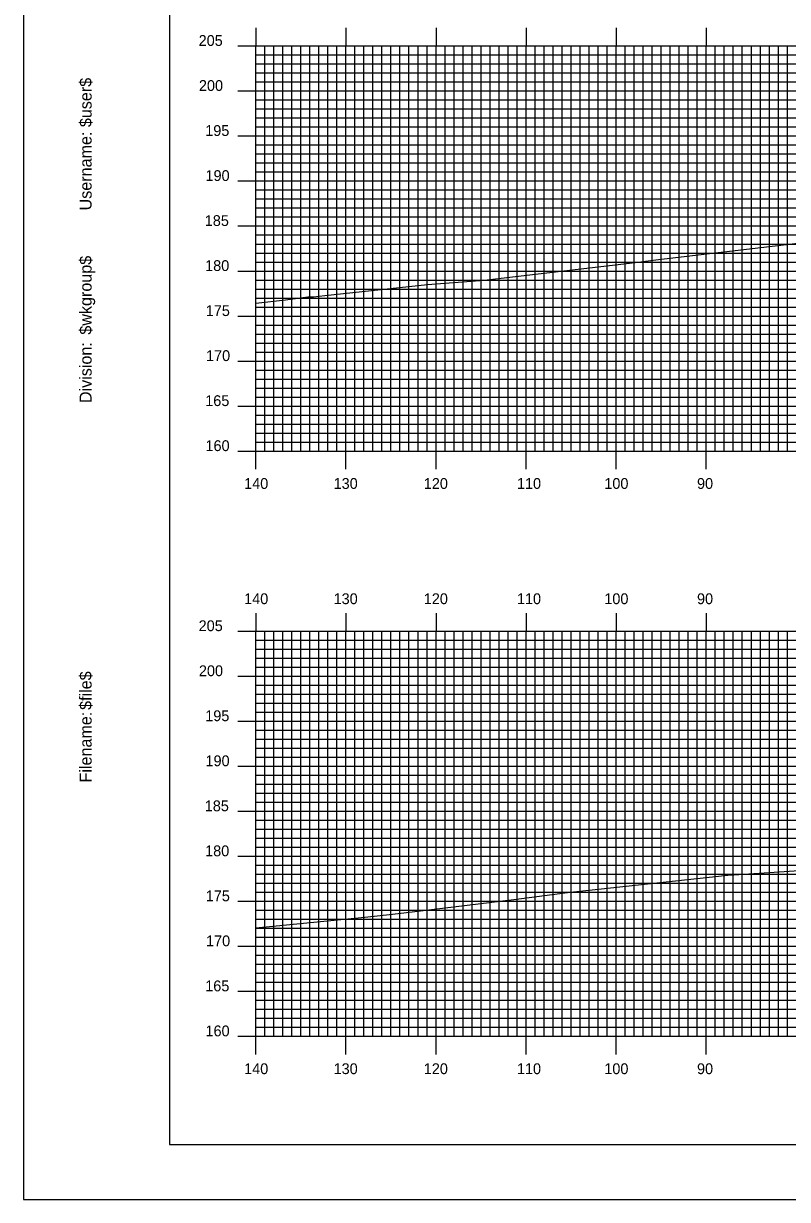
# Model space of a CAD drawing. Extents: x 1794453 to 1794796, y 442591 to 442811.
# Drawn here: x 1794452.6 to 1794537.4, y 442590.5 to 442721.2 of the extents above; entities that cross this region are included whole.
import ezdxf

# ---------------------------------------------------------------- set-up
doc = ezdxf.new("R2010")
doc.units = 0
for name, color, linetype in [('BORDER', 7, 'Continuous'), ('H_V ANNOTATION', 7, 'Continuous'), ('MAJOR', 7, 'Continuous'), ('MINOR', 7, 'Continuous'), ('PLOT BOUNDARY', 7, 'Continuous'), ('S_Roadway_Centerline', 7, 'Continuous')]:
    doc.layers.add(name, color=color, linetype=linetype)

msp = doc.modelspace()

# ---------------------------------------------------------------- linework, layer by layer
at = {"layer": 'BORDER'}
msp.add_lwpolyline([(1794468.74, 442596.67), (1794788.74, 442596.67), (1794788.74, 442806.67), (1794468.74, 442806.67)], close=True, dxfattribs=at)
at = {"layer": 'MAJOR'}
for p, q in [((1794478.34, 442720.67), (1794478.34, 442718.67)), ((1794488.34, 442720.67), (1794488.34, 442718.67)), ((1794498.34, 442720.67), (1794498.34, 442718.67)), ((1794508.34, 442720.67), (1794508.34, 442718.67)), ((1794518.34, 442720.67), (1794518.34, 442718.67)), ((1794528.34, 442720.67), (1794528.34, 442718.67)), ((1794476.34, 442718.67), (1794478.34, 442718.67)), ((1794478.34, 442718.67), (1794758.34, 442718.67)), ((1794478.34, 442673.67), (1794478.34, 442718.67)), ((1794478.34, 442673.67), (1794478.34, 442718.67)), ((1794478.34, 442718.67), (1794758.34, 442718.67)), ((1794488.34, 442673.67), (1794488.34, 442718.67)), ((1794498.34, 442673.67), (1794498.34, 442718.67)), ((1794508.34, 442673.67), (1794508.34, 442718.67)), ((1794518.34, 442673.67), (1794518.34, 442718.67)), ((1794528.34, 442673.67), (1794528.34, 442718.67)), ((1794476.34, 442713.67), (1794478.34, 442713.67)), ((1794478.34, 442713.67), (1794758.34, 442713.67)), ((1794476.34, 442708.67), (1794478.34, 442708.67)), ((1794478.34, 442708.67), (1794758.34, 442708.67)), ((1794476.34, 442703.67), (1794478.34, 442703.67)), ((1794478.34, 442703.67), (1794758.34, 442703.67)), ((1794476.34, 442698.67), (1794478.34, 442698.67)), ((1794478.34, 442698.67), (1794758.34, 442698.67)), ((1794476.34, 442693.67), (1794478.34, 442693.67)), ((1794478.34, 442693.67), (1794758.34, 442693.67)), ((1794476.34, 442688.67), (1794478.34, 442688.67)), ((1794478.34, 442688.67), (1794758.34, 442688.67)), ((1794476.34, 442683.67), (1794478.34, 442683.67)), ((1794478.34, 442683.67), (1794758.34, 442683.67)), ((1794476.34, 442678.67), (1794478.34, 442678.67)), ((1794478.34, 442678.67), (1794758.34, 442678.67)), ((1794476.34, 442673.67), (1794478.34, 442673.67)), ((1794478.34, 442673.67), (1794758.34, 442673.67)), ((1794478.34, 442673.67), (1794758.34, 442673.67)), ((1794478.34, 442671.66), (1794478.34, 442673.67)), ((1794488.34, 442671.66), (1794488.34, 442673.67)), ((1794498.34, 442671.66), (1794498.34, 442673.67)), ((1794508.34, 442671.66), (1794508.34, 442673.67)), ((1794518.34, 442671.66), (1794518.34, 442673.67)), ((1794528.34, 442671.66), (1794528.34, 442673.67)), ((1794478.34, 442655.67), (1794478.34, 442653.67)), ((1794488.34, 442655.67), (1794488.34, 442653.67)), ((1794498.34, 442655.67), (1794498.34, 442653.67)), ((1794508.34, 442655.67), (1794508.34, 442653.67)), ((1794518.34, 442655.67), (1794518.34, 442653.67)), ((1794528.34, 442655.67), (1794528.34, 442653.67)), ((1794476.34, 442653.67), (1794478.34, 442653.67)), ((1794478.34, 442653.67), (1794758.34, 442653.67)), ((1794478.34, 442608.67), (1794478.34, 442653.67)), ((1794478.34, 442608.67), (1794478.34, 442653.67)), ((1794478.34, 442653.67), (1794758.34, 442653.67)), ((1794488.34, 442608.67), (1794488.34, 442653.67)), ((1794498.34, 442608.67), (1794498.34, 442653.67)), ((1794508.34, 442608.67), (1794508.34, 442653.67)), ((1794518.34, 442608.67), (1794518.34, 442653.67)), ((1794528.34, 442608.67), (1794528.34, 442653.67)), ((1794476.34, 442648.67), (1794478.34, 442648.67)), ((1794478.34, 442648.67), (1794758.34, 442648.67)), ((1794476.34, 442643.67), (1794478.34, 442643.67)), ((1794478.34, 442643.67), (1794758.34, 442643.67)), ((1794476.34, 442638.67), (1794478.34, 442638.67)), ((1794478.34, 442638.67), (1794758.34, 442638.67)), ((1794476.34, 442633.67), (1794478.34, 442633.67)), ((1794478.34, 442633.67), (1794758.34, 442633.67)), ((1794476.34, 442628.67), (1794478.34, 442628.67)), ((1794478.34, 442628.67), (1794758.34, 442628.67)), ((1794476.34, 442623.67), (1794478.34, 442623.67)), ((1794478.34, 442623.67), (1794758.34, 442623.67)), ((1794476.34, 442618.67), (1794478.34, 442618.67)), ((1794478.34, 442618.67), (1794758.34, 442618.67)), ((1794476.34, 442613.67), (1794478.34, 442613.67)), ((1794478.34, 442613.67), (1794758.34, 442613.67)), ((1794476.34, 442608.67), (1794478.34, 442608.67)), ((1794478.34, 442608.67), (1794758.34, 442608.67)), ((1794478.34, 442608.67), (1794758.34, 442608.67)), ((1794478.34, 442606.66), (1794478.34, 442608.67)), ((1794488.34, 442606.66), (1794488.34, 442608.67)), ((1794498.34, 442606.66), (1794498.34, 442608.67)), ((1794508.34, 442606.66), (1794508.34, 442608.67)), ((1794518.34, 442606.66), (1794518.34, 442608.67)), ((1794528.34, 442606.66), (1794528.34, 442608.67))]:
    msp.add_line(p, q, dxfattribs=at)
at = {"layer": 'MINOR'}
for p, q in [((1794479.34, 442673.67), (1794479.34, 442718.67)), ((1794480.34, 442673.67), (1794480.34, 442718.67)), ((1794481.34, 442673.67), (1794481.34, 442718.67)), ((1794482.34, 442673.67), (1794482.34, 442718.67)), ((1794483.34, 442673.67), (1794483.34, 442718.67)), ((1794484.34, 442673.67), (1794484.34, 442718.67)), ((1794485.34, 442673.67), (1794485.34, 442718.67)), ((1794486.34, 442673.67), (1794486.34, 442718.67)), ((1794487.34, 442673.67), (1794487.34, 442718.67)), ((1794489.34, 442673.67), (1794489.34, 442718.67)), ((1794490.34, 442673.67), (1794490.34, 442718.67)), ((1794491.34, 442673.67), (1794491.34, 442718.67)), ((1794492.34, 442673.67), (1794492.34, 442718.67)), ((1794493.34, 442673.67), (1794493.34, 442718.67)), ((1794494.34, 442673.67), (1794494.34, 442718.67)), ((1794495.34, 442673.67), (1794495.34, 442718.67)), ((1794496.34, 442673.67), (1794496.34, 442718.67)), ((1794497.34, 442673.67), (1794497.34, 442718.67)), ((1794499.34, 442673.67), (1794499.34, 442718.67)), ((1794500.34, 442673.67), (1794500.34, 442718.67)), ((1794501.34, 442673.67), (1794501.34, 442718.67)), ((1794502.34, 442673.67), (1794502.34, 442718.67)), ((1794503.34, 442673.67), (1794503.34, 442718.67)), ((1794504.34, 442673.67), (1794504.34, 442718.67)), ((1794505.34, 442673.67), (1794505.34, 442718.67)), ((1794506.34, 442673.67), (1794506.34, 442718.67)), ((1794507.34, 442673.67), (1794507.34, 442718.67)), ((1794509.34, 442673.67), (1794509.34, 442718.67)), ((1794510.34, 442673.67), (1794510.34, 442718.67)), ((1794511.34, 442673.67), (1794511.34, 442718.67)), ((1794512.34, 442673.67), (1794512.34, 442718.67)), ((1794513.34, 442673.67), (1794513.34, 442718.67)), ((1794514.34, 442673.67), (1794514.34, 442718.67)), ((1794515.34, 442673.67), (1794515.34, 442718.67)), ((1794516.34, 442673.67), (1794516.34, 442718.67)), ((1794517.34, 442673.67), (1794517.34, 442718.67)), ((1794519.34, 442673.67), (1794519.34, 442718.67)), ((1794520.34, 442673.67), (1794520.34, 442718.67)), ((1794521.34, 442673.67), (1794521.34, 442718.67)), ((1794522.34, 442673.67), (1794522.34, 442718.67)), ((1794523.34, 442673.67), (1794523.34, 442718.67)), ((1794524.34, 442673.67), (1794524.34, 442718.67)), ((1794525.34, 442673.67), (1794525.34, 442718.67)), ((1794526.34, 442673.67), (1794526.34, 442718.67)), ((1794527.34, 442673.67), (1794527.34, 442718.67)), ((1794529.34, 442673.67), (1794529.34, 442718.67)), ((1794530.34, 442673.67), (1794530.34, 442718.67)), ((1794531.34, 442673.67), (1794531.34, 442718.67)), ((1794532.34, 442673.67), (1794532.34, 442718.67)), ((1794533.34, 442673.67), (1794533.34, 442718.67)), ((1794534.34, 442673.67), (1794534.34, 442718.67)), ((1794535.34, 442673.67), (1794535.34, 442718.67)), ((1794536.34, 442673.67), (1794536.34, 442718.67)), ((1794537.34, 442673.67), (1794537.34, 442718.67)), ((1794478.34, 442717.67), (1794758.34, 442717.67)), ((1794478.34, 442717.67), (1794480.34, 442717.67)), ((1794478.34, 442716.67), (1794758.34, 442716.67)), ((1794478.34, 442716.67), (1794480.34, 442716.67)), ((1794478.34, 442715.67), (1794758.34, 442715.67)), ((1794478.34, 442715.67), (1794480.34, 442715.67)), ((1794478.34, 442714.67), (1794758.34, 442714.67)), ((1794478.34, 442714.67), (1794480.34, 442714.67)), ((1794478.34, 442712.67), (1794758.34, 442712.67)), ((1794478.34, 442712.67), (1794480.34, 442712.67)), ((1794478.34, 442711.67), (1794758.34, 442711.67)), ((1794478.34, 442711.67), (1794480.34, 442711.67)), ((1794478.34, 442710.67), (1794758.34, 442710.67)), ((1794478.34, 442710.67), (1794480.34, 442710.67)), ((1794478.34, 442709.67), (1794758.34, 442709.67)), ((1794478.34, 442709.67), (1794480.34, 442709.67)), ((1794478.34, 442707.67), (1794758.34, 442707.67)), ((1794478.34, 442707.67), (1794480.34, 442707.67)), ((1794478.34, 442706.67), (1794758.34, 442706.67)), ((1794478.34, 442706.67), (1794480.34, 442706.67)), ((1794478.34, 442705.67), (1794758.34, 442705.67)), ((1794478.34, 442705.67), (1794480.34, 442705.67)), ((1794478.34, 442704.67), (1794758.34, 442704.67)), ((1794478.34, 442704.67), (1794480.34, 442704.67)), ((1794478.34, 442702.67), (1794758.34, 442702.67)), ((1794478.34, 442702.67), (1794480.34, 442702.67)), ((1794478.34, 442701.67), (1794758.34, 442701.67)), ((1794478.34, 442701.67), (1794480.34, 442701.67)), ((1794478.34, 442700.67), (1794758.34, 442700.67)), ((1794478.34, 442700.67), (1794480.34, 442700.67)), ((1794478.34, 442699.67), (1794758.34, 442699.67)), ((1794478.34, 442699.67), (1794480.34, 442699.67)), ((1794478.34, 442697.67), (1794758.34, 442697.67)), ((1794478.34, 442697.67), (1794480.34, 442697.67)), ((1794478.34, 442696.67), (1794758.34, 442696.67)), ((1794478.34, 442696.67), (1794480.34, 442696.67)), ((1794478.34, 442695.67), (1794758.34, 442695.67)), ((1794478.34, 442695.67), (1794480.34, 442695.67)), ((1794478.34, 442694.67), (1794758.34, 442694.67)), ((1794478.34, 442694.67), (1794480.34, 442694.67)), ((1794478.34, 442692.67), (1794758.34, 442692.67)), ((1794478.34, 442692.67), (1794480.34, 442692.67)), ((1794478.34, 442691.67), (1794758.34, 442691.67)), ((1794478.34, 442691.67), (1794480.34, 442691.67)), ((1794478.34, 442690.67), (1794758.34, 442690.67)), ((1794478.34, 442690.67), (1794480.34, 442690.67)), ((1794478.34, 442689.67), (1794758.34, 442689.67)), ((1794478.34, 442689.67), (1794480.34, 442689.67)), ((1794478.34, 442687.67), (1794758.34, 442687.67)), ((1794478.34, 442687.67), (1794480.34, 442687.67)), ((1794478.34, 442686.67), (1794758.34, 442686.67)), ((1794478.34, 442686.67), (1794480.34, 442686.67)), ((1794478.34, 442685.67), (1794758.34, 442685.67)), ((1794478.34, 442685.67), (1794480.34, 442685.67)), ((1794478.34, 442684.67), (1794758.34, 442684.67)), ((1794478.34, 442684.67), (1794480.34, 442684.67)), ((1794478.34, 442682.67), (1794758.34, 442682.67)), ((1794478.34, 442682.67), (1794480.34, 442682.67)), ((1794478.34, 442681.67), (1794758.34, 442681.67)), ((1794478.34, 442681.67), (1794480.34, 442681.67)), ((1794478.34, 442680.67), (1794758.34, 442680.67)), ((1794478.34, 442680.67), (1794480.34, 442680.67)), ((1794478.34, 442679.67), (1794758.34, 442679.67)), ((1794478.34, 442679.67), (1794480.34, 442679.67)), ((1794478.34, 442677.67), (1794758.34, 442677.67)), ((1794478.34, 442677.67), (1794480.34, 442677.67)), ((1794478.34, 442676.67), (1794758.34, 442676.67)), ((1794478.34, 442676.67), (1794480.34, 442676.67)), ((1794478.34, 442675.67), (1794758.34, 442675.67)), ((1794478.34, 442675.67), (1794480.34, 442675.67)), ((1794478.34, 442674.67), (1794758.34, 442674.67)), ((1794478.34, 442674.67), (1794480.34, 442674.67)), ((1794478.34, 442652.67), (1794758.34, 442652.67)), ((1794478.34, 442652.67), (1794480.34, 442652.67)), ((1794479.34, 442608.67), (1794479.34, 442653.67)), ((1794480.34, 442608.67), (1794480.34, 442653.67)), ((1794481.34, 442608.67), (1794481.34, 442653.67)), ((1794482.34, 442608.67), (1794482.34, 442653.67)), ((1794483.34, 442608.67), (1794483.34, 442653.67)), ((1794484.34, 442608.67), (1794484.34, 442653.67)), ((1794485.34, 442608.67), (1794485.34, 442653.67)), ((1794486.34, 442608.67), (1794486.34, 442653.67)), ((1794487.34, 442608.67), (1794487.34, 442653.67)), ((1794489.34, 442608.67), (1794489.34, 442653.67)), ((1794490.34, 442608.67), (1794490.34, 442653.67)), ((1794491.34, 442608.67), (1794491.34, 442653.67)), ((1794492.34, 442608.67), (1794492.34, 442653.67)), ((1794493.34, 442608.67), (1794493.34, 442653.67)), ((1794494.34, 442608.67), (1794494.34, 442653.67)), ((1794495.34, 442608.67), (1794495.34, 442653.67)), ((1794496.34, 442608.67), (1794496.34, 442653.67)), ((1794497.34, 442608.67), (1794497.34, 442653.67)), ((1794499.34, 442608.67), (1794499.34, 442653.67)), ((1794500.34, 442608.67), (1794500.34, 442653.67)), ((1794501.34, 442608.67), (1794501.34, 442653.67)), ((1794502.34, 442608.67), (1794502.34, 442653.67)), ((1794503.34, 442608.67), (1794503.34, 442653.67)), ((1794504.34, 442608.67), (1794504.34, 442653.67)), ((1794505.34, 442608.67), (1794505.34, 442653.67)), ((1794506.34, 442608.67), (1794506.34, 442653.67)), ((1794507.34, 442608.67), (1794507.34, 442653.67)), ((1794509.34, 442608.67), (1794509.34, 442653.67)), ((1794510.34, 442608.67), (1794510.34, 442653.67)), ((1794511.34, 442608.67), (1794511.34, 442653.67)), ((1794512.34, 442608.67), (1794512.34, 442653.67)), ((1794513.34, 442608.67), (1794513.34, 442653.67)), ((1794514.34, 442608.67), (1794514.34, 442653.67)), ((1794515.34, 442608.67), (1794515.34, 442653.67)), ((1794516.34, 442608.67), (1794516.34, 442653.67)), ((1794517.34, 442608.67), (1794517.34, 442653.67)), ((1794519.34, 442608.67), (1794519.34, 442653.67)), ((1794520.34, 442608.67), (1794520.34, 442653.67)), ((1794521.34, 442608.67), (1794521.34, 442653.67)), ((1794522.34, 442608.67), (1794522.34, 442653.67)), ((1794523.34, 442608.67), (1794523.34, 442653.67)), ((1794524.34, 442608.67), (1794524.34, 442653.67)), ((1794525.34, 442608.67), (1794525.34, 442653.67)), ((1794526.34, 442608.67), (1794526.34, 442653.67)), ((1794527.34, 442608.67), (1794527.34, 442653.67)), ((1794529.34, 442608.67), (1794529.34, 442653.67)), ((1794530.34, 442608.67), (1794530.34, 442653.67)), ((1794531.34, 442608.67), (1794531.34, 442653.67)), ((1794532.34, 442608.67), (1794532.34, 442653.67)), ((1794533.34, 442608.67), (1794533.34, 442653.67)), ((1794534.34, 442608.67), (1794534.34, 442653.67)), ((1794535.34, 442608.67), (1794535.34, 442653.67)), ((1794536.34, 442608.67), (1794536.34, 442653.67)), ((1794537.34, 442608.67), (1794537.34, 442653.67)), ((1794478.34, 442651.67), (1794758.34, 442651.67)), ((1794478.34, 442651.67), (1794480.34, 442651.67)), ((1794478.34, 442650.67), (1794758.34, 442650.67)), ((1794478.34, 442650.67), (1794480.34, 442650.67)), ((1794478.34, 442649.67), (1794758.34, 442649.67)), ((1794478.34, 442649.67), (1794480.34, 442649.67)), ((1794478.34, 442647.67), (1794758.34, 442647.67)), ((1794478.34, 442647.67), (1794480.34, 442647.67)), ((1794478.34, 442646.67), (1794758.34, 442646.67)), ((1794478.34, 442646.67), (1794480.34, 442646.67)), ((1794478.34, 442645.67), (1794758.34, 442645.67)), ((1794478.34, 442645.67), (1794480.34, 442645.67)), ((1794478.34, 442644.67), (1794758.34, 442644.67)), ((1794478.34, 442644.67), (1794480.34, 442644.67)), ((1794478.34, 442642.67), (1794758.34, 442642.67)), ((1794478.34, 442642.67), (1794480.34, 442642.67)), ((1794478.34, 442641.67), (1794758.34, 442641.67)), ((1794478.34, 442641.67), (1794480.34, 442641.67)), ((1794478.34, 442640.67), (1794758.34, 442640.67)), ((1794478.34, 442640.67), (1794480.34, 442640.67)), ((1794478.34, 442639.67), (1794758.34, 442639.67)), ((1794478.34, 442639.67), (1794480.34, 442639.67)), ((1794478.34, 442637.67), (1794758.34, 442637.67)), ((1794478.34, 442637.67), (1794480.34, 442637.67)), ((1794478.34, 442636.67), (1794758.34, 442636.67)), ((1794478.34, 442636.67), (1794480.34, 442636.67)), ((1794478.34, 442635.67), (1794758.34, 442635.67)), ((1794478.34, 442635.67), (1794480.34, 442635.67)), ((1794478.34, 442634.67), (1794758.34, 442634.67)), ((1794478.34, 442634.67), (1794480.34, 442634.67)), ((1794478.34, 442632.67), (1794758.34, 442632.67)), ((1794478.34, 442632.67), (1794480.34, 442632.67)), ((1794478.34, 442631.67), (1794758.34, 442631.67)), ((1794478.34, 442631.67), (1794480.34, 442631.67)), ((1794478.34, 442630.67), (1794758.34, 442630.67)), ((1794478.34, 442630.67), (1794480.34, 442630.67)), ((1794478.34, 442629.67), (1794758.34, 442629.67)), ((1794478.34, 442629.67), (1794480.34, 442629.67)), ((1794478.34, 442627.67), (1794758.34, 442627.67)), ((1794478.34, 442627.67), (1794480.34, 442627.67)), ((1794478.34, 442626.67), (1794758.34, 442626.67)), ((1794478.34, 442626.67), (1794480.34, 442626.67)), ((1794478.34, 442625.67), (1794758.34, 442625.67)), ((1794478.34, 442625.67), (1794480.34, 442625.67)), ((1794478.34, 442624.67), (1794758.34, 442624.67)), ((1794478.34, 442624.67), (1794480.34, 442624.67)), ((1794478.34, 442622.67), (1794758.34, 442622.67)), ((1794478.34, 442622.67), (1794480.34, 442622.67)), ((1794478.34, 442621.67), (1794758.34, 442621.67)), ((1794478.34, 442621.67), (1794480.34, 442621.67)), ((1794478.34, 442620.67), (1794758.34, 442620.67)), ((1794478.34, 442620.67), (1794480.34, 442620.67)), ((1794478.34, 442619.67), (1794758.34, 442619.67)), ((1794478.34, 442619.67), (1794480.34, 442619.67)), ((1794478.34, 442617.67), (1794758.34, 442617.67)), ((1794478.34, 442617.67), (1794480.34, 442617.67)), ((1794478.34, 442616.67), (1794758.34, 442616.67)), ((1794478.34, 442616.67), (1794480.34, 442616.67)), ((1794478.34, 442615.67), (1794758.34, 442615.67)), ((1794478.34, 442615.67), (1794480.34, 442615.67)), ((1794478.34, 442614.67), (1794758.34, 442614.67)), ((1794478.34, 442614.67), (1794480.34, 442614.67)), ((1794478.34, 442612.67), (1794758.34, 442612.67)), ((1794478.34, 442612.67), (1794480.34, 442612.67)), ((1794478.34, 442611.67), (1794758.34, 442611.67)), ((1794478.34, 442611.67), (1794480.34, 442611.67)), ((1794478.34, 442610.67), (1794758.34, 442610.67)), ((1794478.34, 442610.67), (1794480.34, 442610.67)), ((1794478.34, 442609.67), (1794758.34, 442609.67)), ((1794478.34, 442609.67), (1794480.34, 442609.67))]:
    msp.add_line(p, q, dxfattribs=at)
at = {"layer": 'PLOT BOUNDARY'}
msp.add_lwpolyline([(1794452.55, 442590.55), (1794792.55, 442590.55), (1794792.55, 442810.55), (1794452.55, 442810.55)], close=True, dxfattribs=at)
at = {"layer": 'S_Roadway_Centerline'}
for points in [[(1794478.34, 442690.11), (1794481.65, 442690.48), (1794484.12, 442690.79), (1794484.74, 442690.82), (1794486, 442690.96), (1794497.41, 442692.18), (1794503.67, 442692.66), (1794521.06, 442694.7), (1794521.61, 442694.78), (1794521.9, 442694.81), (1794523.03, 442694.94), (1794540.4, 442696.97)], [(1794478.34, 442620.7), (1794490.44, 442621.92), (1794493.51, 442622.22), (1794496.61, 442622.59), (1794506.97, 442623.87), (1794512.93, 442624.64), (1794531.05, 442626.59), (1794531.32, 442626.62), (1794531.41, 442626.62), (1794542.56, 442627.35)]]:
    msp.add_lwpolyline(points, dxfattribs=at)

# ---------------------------------------------------------------- texts
at = {"layer": 'BORDER'}
for s, p in [('$user$', (1794460.11, 442709.65)), ('Username:', (1794460.11, 442700.4)), ('$wkgroup$', (1794460.11, 442686.6)), ('Division:', (1794460.11, 442679)), ('$file$', (1794460.11, 442644.92)), ('Filename:', (1794460.11, 442636.86))]:
    msp.add_text(s, height=1.339, rotation=90, dxfattribs=at).set_placement(p)
at = {"layer": 'H_V ANNOTATION'}
for s, p in [('205', (1794471.99, 442718.67)), ('200', (1794472.02, 442713.67)), ('195', (1794472.72, 442708.67)), ('190', (1794472.75, 442703.67)), ('185', (1794472.67, 442698.67)), ('180', (1794472.71, 442693.67)), ('175', (1794472.78, 442688.67)), ('170', (1794472.81, 442683.67)), ('165', (1794472.72, 442678.67)), ('160', (1794472.75, 442673.67)), ('140', (1794477.04, 442669.47)), ('130', (1794486.97, 442669.47)), ('120', (1794496.98, 442669.47)), ('110', (1794507.32, 442669.47)), ('100', (1794517.02, 442669.47)), ('90', (1794527.31, 442669.47)), ('140', (1794477.04, 442656.67)), ('130', (1794486.97, 442656.67)), ('120', (1794496.98, 442656.67)), ('110', (1794507.32, 442656.67)), ('100', (1794517.02, 442656.67)), ('90', (1794527.31, 442656.67)), ('205', (1794471.99, 442653.67)), ('200', (1794472.02, 442648.67)), ('195', (1794472.72, 442643.67)), ('190', (1794472.75, 442638.67)), ('185', (1794472.67, 442633.67)), ('180', (1794472.71, 442628.67)), ('175', (1794472.78, 442623.67)), ('170', (1794472.81, 442618.67)), ('165', (1794472.72, 442613.67)), ('160', (1794472.75, 442608.67)), ('140', (1794477.04, 442604.47)), ('130', (1794486.97, 442604.47)), ('120', (1794496.98, 442604.47)), ('110', (1794507.32, 442604.47)), ('100', (1794517.02, 442604.47)), ('90', (1794527.31, 442604.47))]:
    msp.add_text(s, height=1.2, dxfattribs=at).set_placement(p)
at = {"layer": 'MAJOR'}
for p in [(1794478.33, 442673.67), (1794478.33, 442608.67)]:
    msp.add_text('-', height=0.012, dxfattribs=at).set_placement(p)

doc.saveas('drawing.dxf')
